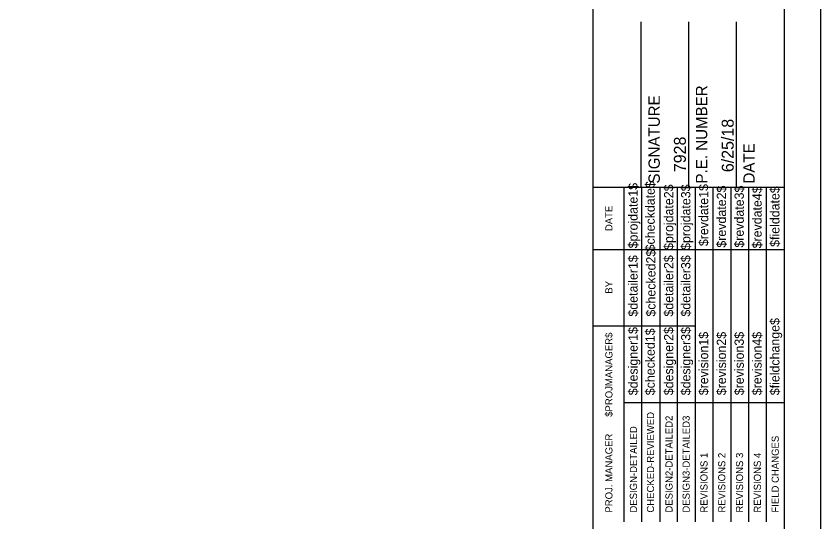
# Model space of a CAD drawing. Extents: x 916257 to 917115, y 329394 to 329944.
# Drawn here: x 916896.6 to 917107, y 329634.2 to 329766.4 of the extents above; entities that cross this region are included whole.
import ezdxf

# ---------------------------------------------------------------- set-up
doc = ezdxf.new("R2010")
doc.units = 0
doc.layers.add('Border', color=7, linetype='Continuous')
doc.layers.add('PLOT BOUNDARY', color=7, linetype='Continuous')

msp = doc.modelspace()

# ---------------------------------------------------------------- linework, layer by layer
at = {"layer": 'Border'}
for p, q in [((917047.47, 329409.22), (917047.47, 329934.22)), ((917097.47, 329409.22), (917097.47, 329934.22)), ((917059.97, 329721.72), (917059.97, 329764.96)), ((917072.47, 329721.72), (917072.47, 329764.96)), ((917084.97, 329721.72), (917084.97, 329764.96)), ((917047.47, 329721.72), (917097.47, 329721.72))]:
    msp.add_line(p, q, dxfattribs=at)
for points in [[(917055.54, 329705.47), (917055.54, 329721.72)], [(917060.2, 329634.24), (917060.2, 329721.72)], [(917064.86, 329721.72), (917064.86, 329634.24)], [(917069.52, 329634.24), (917069.52, 329721.72)], [(917074.18, 329634.24), (917074.18, 329721.72)], [(917078.84, 329634.24), (917078.84, 329721.72)], [(917083.5, 329634.24), (917083.5, 329721.72)], [(917088.15, 329634.24), (917088.15, 329721.72)], [(917092.81, 329634.24), (917092.81, 329721.72)], [(917055.54, 329634.24), (917055.54, 329718.19)], [(917047.47, 329705.47), (917097.47, 329705.47)], [(917047.47, 329685.47), (917055.54, 329685.47)], [(917055.54, 329685.47), (917074.17, 329685.47)], [(917055.54, 329665.47), (917097.47, 329665.47)]]:
    msp.add_lwpolyline(points, dxfattribs=at)
at = {"layer": 'PLOT BOUNDARY'}
msp.add_lwpolyline([(916257, 329393.91), (917107, 329393.91), (917107, 329943.91), (916257, 329943.91)], close=True, dxfattribs=at)

# ---------------------------------------------------------------- texts
at = {"layer": 'Border'}
for s, height, p in [('P.E. NUMBER', 2.9528, (917077.27, 329722.68)), ('SIGNATURE', 2.953, (917064.87, 329722.68)), ('6/25/18', 3.125, (917084.19, 329725.65)), ('7928', 3.125, (917071.69, 329725.65)), ('DATE', 2.953, (917089.67, 329722.68)), ('$projdate1$', 2.4227, (917059.08, 329705.73)), ('$checkdate$', 2.4227, (917063.55, 329704.94)), ('$projdate2$', 2.4227, (917068.4, 329705.33)), ('$projdate3$', 2.4227, (917072.87, 329705.33)), ('$revdate1$', 2.423, (917077.53, 329706.32)), ('$revdate2$', 2.423, (917082.19, 329705.92)), ('$revdate3$', 2.423, (917086.84, 329705.92)), ('$revdate4$', 2.423, (917091.5, 329705.73)), ('$fielddate$', 2.4227, (917096.16, 329706.12)), ('DATE', 1.857, (917052.49, 329710.25)), ('$checked2$', 2.423, (917063.74, 329687.9)), ('$detailer1$', 2.4227, (917059.08, 329687.9)), ('$detailer2$', 2.4227, (917068.4, 329687.9)), ('$detailer3$', 2.4227, (917072.87, 329687.9)), ('BY', 1.857, (917052.49, 329693.9)), ('$fieldchange$', 2.4227, (917096.16, 329667.34)), ('$PROJMANAGER$', 1.8637, (917052.49, 329661.7)), ('$designer1$', 2.4227, (917059.08, 329667.34)), ('$checked1$', 2.423, (917063.55, 329667.34)), ('$designer2$', 2.4227, (917068.4, 329667.34)), ('$designer3$', 2.4227, (917072.87, 329667.34)), ('$revision1$', 2.4227, (917077.53, 329667.34)), ('$revision2$', 2.4227, (917082.19, 329667.34)), ('$revision3$', 2.4227, (917086.84, 329667.34)), ('$revision4$', 2.4227, (917091.5, 329667.34)), ('CHECKED-REVIEWED', 1.8637, (917063.37, 329636.66)), ('DESIGN2-DETAILED2', 1.8637, (917068.22, 329636.66)), ('DESIGN3-DETAILED3', 1.8637, (917072.69, 329636.66)), ('DESIGN-DETAILED', 1.8637, (917058.9, 329636.66)), ('PROJ. MANAGER', 1.8637, (917052.49, 329636.66)), ('FIELD CHANGES', 1.8637, (917095.98, 329636.66)), ('REVISIONS 1', 1.8637, (917077.35, 329636.66)), ('REVISIONS 2', 1.8637, (917082, 329636.66)), ('REVISIONS 3', 1.8637, (917086.66, 329636.66)), ('REVISIONS 4', 1.8637, (917091.32, 329636.66))]:
    msp.add_text(s, height=height, rotation=90, dxfattribs=at).set_placement(p)

doc.saveas('drawing.dxf')
